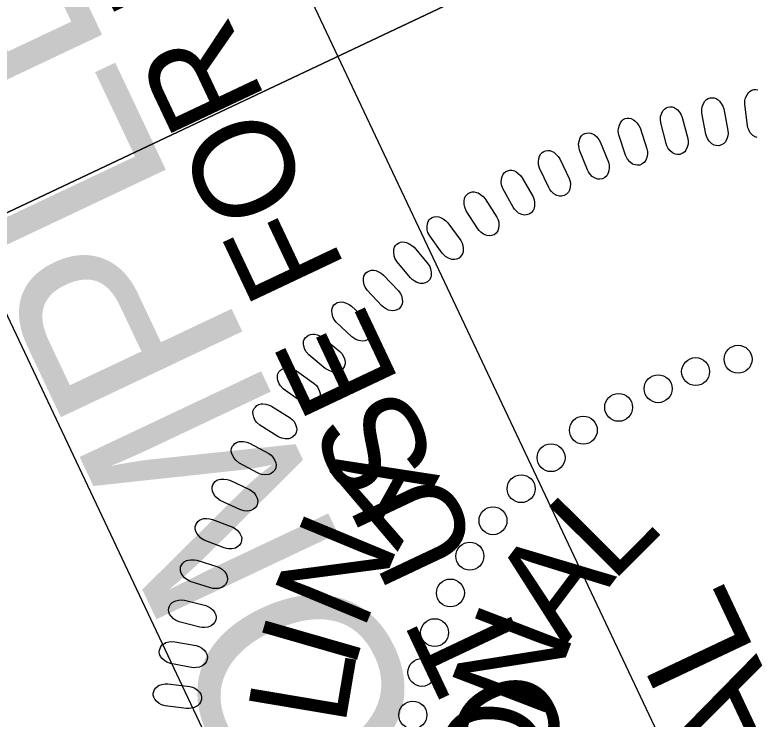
# Model space of a CAD drawing. Extents: x 476855 to 478565, y 498324 to 500313.
# Drawn here: x 476991.92 to 477034.48, y 499751.49 to 499791.92 of the extents above; entities that cross this region are included whole.
import ezdxf

# ---------------------------------------------------------------- set-up
doc = ezdxf.new("R2010")
doc.units = 0
for name, color, linetype in [('Sheet PE Seal Cell', 7, 'Continuous'), ('Sheet Plan CELL', 7, 'Continuous'), ('Sheet Sticker Incomplete CELL', 7, 'Continuous')]:
    doc.layers.add(name, color=color, linetype=linetype)

msp = doc.modelspace()

# ---------------------------------------------------------------- linework, layer by layer
at = {"layer": 'Sheet PE Seal Cell'}
msp.add_lwpolyline([(477034.529, 499784.874), (477034.419, 499784.91), (477034.28, 499784.993), (477034.141, 499785.146), (477034.051, 499785.316), (477034.005, 499785.44), (477033.974, 499785.567), (477033.818, 499786.784), (477033.828, 499787.006), (477033.861, 499787.152), (477033.952, 499787.334), (477034.034, 499787.455), (477034.135, 499787.548), (477034.234, 499787.601), (477034.342, 499787.635), (477034.456, 499787.629), (477034.579, 499787.614)], dxfattribs=at)
for points in [[(477031.59, 499785.073), (477031.358, 499786.278), (477031.354, 499786.5), (477031.378, 499786.648), (477031.456, 499786.836), (477031.531, 499786.961), (477031.627, 499787.061), (477031.721, 499787.119), (477031.828, 499787.16), (477031.941, 499787.162), (477032.065, 499787.155), (477032.179, 499787.116), (477032.3, 499787.038), (477032.374, 499786.971), (477032.469, 499786.836), (477032.561, 499786.672), (477032.613, 499786.519), (477032.858, 499785.287), (477032.867, 499785.116), (477032.85, 499784.97), (477032.792, 499784.797), (477032.708, 499784.639), (477032.628, 499784.542), (477032.485, 499784.453), (477032.342, 499784.405), (477032.187, 499784.416), (477032.075, 499784.446), (477031.931, 499784.519), (477031.783, 499784.664), (477031.682, 499784.828), (477031.629, 499784.949)], [(477029.305, 499784.526), (477028.999, 499785.714), (477028.98, 499785.935), (477028.995, 499786.084), (477029.062, 499786.276), (477029.129, 499786.407), (477029.217, 499786.512), (477029.308, 499786.577), (477029.412, 499786.624), (477029.525, 499786.633), (477029.649, 499786.634), (477029.765, 499786.602), (477029.891, 499786.531), (477029.969, 499786.469), (477030.072, 499786.341), (477030.174, 499786.182), (477030.236, 499786.034), (477030.557, 499784.819), (477030.578, 499784.649), (477030.569, 499784.502), (477030.522, 499784.325), (477030.449, 499784.162), (477030.375, 499784.061), (477030.238, 499783.963), (477030.098, 499783.907), (477029.943, 499783.908), (477029.829, 499783.93), (477029.681, 499783.995), (477029.524, 499784.129), (477029.413, 499784.287), (477029.353, 499784.404)], [(477026.977, 499783.865), (477026.597, 499785.031), (477026.564, 499785.251), (477026.57, 499785.4), (477026.624, 499785.597), (477026.683, 499785.731), (477026.764, 499785.841), (477026.851, 499785.912), (477026.953, 499785.965), (477027.065, 499785.981), (477027.188, 499785.99), (477027.306, 499785.966), (477027.436, 499785.903), (477027.517, 499785.846), (477027.628, 499785.725), (477027.74, 499785.573), (477027.812, 499785.428), (477028.208, 499784.235), (477028.24, 499784.067), (477028.24, 499783.92), (477028.205, 499783.741), (477028.142, 499783.574), (477028.074, 499783.468), (477027.943, 499783.362), (477027.807, 499783.297), (477027.652, 499783.289), (477027.538, 499783.303), (477027.386, 499783.358), (477027.22, 499783.483), (477027.1, 499783.633), (477027.032, 499783.747)], [(477024.791, 499783.016), (477024.337, 499784.156), (477024.292, 499784.373), (477024.288, 499784.522), (477024.33, 499784.722), (477024.38, 499784.86), (477024.454, 499784.975), (477024.536, 499785.05), (477024.634, 499785.111), (477024.745, 499785.133), (477024.867, 499785.15), (477024.987, 499785.133), (477025.121, 499785.079), (477025.206, 499785.027), (477025.324, 499784.912), (477025.446, 499784.768), (477025.525, 499784.627), (477025.996, 499783.463), (477026.038, 499783.297), (477026.048, 499783.15), (477026.024, 499782.969), (477025.971, 499782.798), (477025.91, 499782.688), (477025.786, 499782.574), (477025.654, 499782.501), (477025.501, 499782.483), (477025.385, 499782.49), (477025.231, 499782.536), (477025.057, 499782.649), (477024.928, 499782.792), (477024.853, 499782.9)], [(477022.57, 499782.003), (477022.046, 499783.113), (477021.986, 499783.327), (477021.974, 499783.475), (477022.003, 499783.677), (477022.043, 499783.817), (477022.111, 499783.937), (477022.189, 499784.017), (477022.282, 499784.084), (477022.392, 499784.113), (477022.513, 499784.138), (477022.633, 499784.128), (477022.77, 499784.083), (477022.858, 499784.036), (477022.983, 499783.929), (477023.114, 499783.793), (477023.202, 499783.658), (477023.746, 499782.525), (477023.797, 499782.362), (477023.816, 499782.216), (477023.803, 499782.034), (477023.762, 499781.86), (477023.708, 499781.746), (477023.592, 499781.625), (477023.465, 499781.543), (477023.312, 499781.516), (477023.197, 499781.516), (477023.039, 499781.551), (477022.859, 499781.654), (477022.721, 499781.788), (477022.639, 499781.892)], [(477020.527, 499780.872), (477019.935, 499781.947), (477019.862, 499782.157), (477019.839, 499782.304), (477019.856, 499782.507), (477019.888, 499782.65), (477019.948, 499782.774), (477020.02, 499782.859), (477020.109, 499782.931), (477020.216, 499782.968), (477020.336, 499782.999), (477020.456, 499782.997), (477020.596, 499782.961), (477020.687, 499782.919), (477020.818, 499782.821), (477020.957, 499782.693), (477021.054, 499782.564), (477021.667, 499781.467), (477021.729, 499781.308), (477021.757, 499781.163), (477021.756, 499780.981), (477021.725, 499780.805), (477021.679, 499780.688), (477021.57, 499780.559), (477021.448, 499780.47), (477021.299, 499780.433), (477021.183, 499780.426), (477021.023, 499780.452), (477020.837, 499780.542), (477020.691, 499780.667), (477020.602, 499780.766)], [(477018.493, 499779.642), (477017.834, 499780.677), (477017.748, 499780.882), (477017.717, 499781.028), (477017.72, 499781.231), (477017.743, 499781.376), (477017.795, 499781.503), (477017.862, 499781.593), (477017.946, 499781.67), (477018.051, 499781.713), (477018.168, 499781.752), (477018.289, 499781.759), (477018.43, 499781.73), (477018.523, 499781.695), (477018.661, 499781.605), (477018.808, 499781.486), (477018.913, 499781.363), (477019.594, 499780.307), (477019.665, 499780.152), (477019.702, 499780.01), (477019.712, 499779.827), (477019.693, 499779.649), (477019.654, 499779.53), (477019.554, 499779.395), (477019.438, 499779.298), (477019.29, 499779.251), (477019.175, 499779.238), (477019.015, 499779.253), (477018.823, 499779.332), (477018.67, 499779.447), (477018.575, 499779.541)], [(477016.457, 499778.24), (477015.735, 499779.231), (477015.636, 499779.431), (477015.596, 499779.574), (477015.587, 499779.777), (477015.601, 499779.923), (477015.644, 499780.054), (477015.705, 499780.147), (477015.784, 499780.23), (477015.887, 499780.279), (477016.002, 499780.326), (477016.121, 499780.339), (477016.264, 499780.32), (477016.359, 499780.291), (477016.502, 499780.209), (477016.656, 499780.099), (477016.768, 499779.984), (477017.514, 499778.972), (477017.596, 499778.822), (477017.641, 499778.683), (477017.663, 499778.501), (477017.655, 499778.323), (477017.623, 499778.201), (477017.532, 499778.059), (477017.422, 499777.956), (477017.278, 499777.9), (477017.164, 499777.879), (477017.003, 499777.884), (477016.807, 499777.951), (477016.645, 499778.057), (477016.546, 499778.144)], [(477014.637, 499776.816), (477013.854, 499777.76), (477013.743, 499777.952), (477013.693, 499778.093), (477013.671, 499778.296), (477013.676, 499778.442), (477013.712, 499778.575), (477013.767, 499778.672), (477013.841, 499778.759), (477013.939, 499778.816), (477014.051, 499778.869), (477014.169, 499778.89), (477014.313, 499778.88), (477014.411, 499778.857), (477014.558, 499778.784), (477014.719, 499778.684), (477014.838, 499778.576), (477015.645, 499777.614), (477015.736, 499777.469), (477015.791, 499777.333), (477015.824, 499777.153), (477015.827, 499776.974), (477015.803, 499776.85), (477015.721, 499776.704), (477015.618, 499776.593), (477015.477, 499776.529), (477015.365, 499776.5), (477015.204, 499776.496), (477015.004, 499776.549), (477014.837, 499776.645), (477014.731, 499776.726)], [(477012.991, 499775.214), (477012.149, 499776.107), (477012.026, 499776.293), (477011.968, 499776.43), (477011.934, 499776.63), (477011.929, 499776.777), (477011.956, 499776.912), (477012.005, 499777.012), (477012.074, 499777.104), (477012.169, 499777.166), (477012.276, 499777.226), (477012.393, 499777.254), (477012.538, 499777.254), (477012.636, 499777.237), (477012.789, 499777.174), (477012.954, 499777.084), (477013.081, 499776.984), (477013.947, 499776.074), (477014.047, 499775.935), (477014.109, 499775.802), (477014.154, 499775.625), (477014.168, 499775.447), (477014.152, 499775.321), (477014.079, 499775.17), (477013.984, 499775.053), (477013.847, 499774.98), (477013.737, 499774.945), (477013.576, 499774.93), (477013.373, 499774.971), (477013.2, 499775.056), (477013.09, 499775.13)], [(477011.272, 499773.435), (477010.376, 499774.273), (477010.242, 499774.451), (477010.175, 499774.584), (477010.128, 499774.782), (477010.115, 499774.928), (477010.133, 499775.064), (477010.176, 499775.168), (477010.238, 499775.264), (477010.329, 499775.331), (477010.433, 499775.398), (477010.547, 499775.434), (477010.692, 499775.442), (477010.791, 499775.431), (477010.947, 499775.378), (477011.119, 499775.299), (477011.25, 499775.206), (477012.172, 499774.353), (477012.281, 499774.221), (477012.352, 499774.092), (477012.407, 499773.918), (477012.433, 499773.741), (477012.424, 499773.615), (477012.36, 499773.459), (477012.273, 499773.337), (477012.142, 499773.255), (477012.033, 499773.213), (477011.874, 499773.188), (477011.669, 499773.217), (477011.491, 499773.29), (477011.376, 499773.357)], [(477009.736, 499771.626), (477008.79, 499772.406), (477008.645, 499772.575), (477008.57, 499772.704), (477008.511, 499772.899), (477008.488, 499773.043), (477008.498, 499773.181), (477008.533, 499773.287), (477008.59, 499773.386), (477008.676, 499773.46), (477008.776, 499773.533), (477008.888, 499773.576), (477009.032, 499773.593), (477009.131, 499773.588), (477009.29, 499773.545), (477009.466, 499773.476), (477009.603, 499773.392), (477010.578, 499772.598), (477010.694, 499772.473), (477010.773, 499772.35), (477010.839, 499772.179), (477010.875, 499772.004), (477010.875, 499771.878), (477010.821, 499771.719), (477010.741, 499771.591), (477010.616, 499771.501), (477010.51, 499771.452), (477010.353, 499771.417), (477010.146, 499771.433), (477009.964, 499771.495), (477009.846, 499771.555)], [(477008.326, 499769.735), (477007.333, 499770.454), (477007.177, 499770.614), (477007.094, 499770.737), (477007.022, 499770.928), (477006.991, 499771.071), (477006.992, 499771.209), (477007.022, 499771.317), (477007.071, 499771.419), (477007.153, 499771.498), (477007.247, 499771.577), (477007.357, 499771.627), (477007.499, 499771.654), (477007.599, 499771.655), (477007.76, 499771.622), (477007.94, 499771.565), (477008.082, 499771.49), (477009.104, 499770.758), (477009.229, 499770.64), (477009.316, 499770.522), (477009.391, 499770.356), (477009.439, 499770.184), (477009.447, 499770.058), (477009.403, 499769.896), (477009.332, 499769.763), (477009.212, 499769.665), (477009.11, 499769.609), (477008.954, 499769.565), (477008.747, 499769.568), (477008.562, 499769.619), (477008.439, 499769.671)], [(477007.012, 499767.719), (477005.975, 499768.374), (477005.809, 499768.524), (477005.719, 499768.642), (477005.636, 499768.828), (477005.595, 499768.969), (477005.587, 499769.106), (477005.61, 499769.216), (477005.653, 499769.321), (477005.73, 499769.405), (477005.819, 499769.49), (477005.925, 499769.547), (477006.066, 499769.582), (477006.165, 499769.59), (477006.328, 499769.566), (477006.511, 499769.521), (477006.658, 499769.455), (477007.724, 499768.79), (477007.855, 499768.68), (477007.949, 499768.567), (477008.036, 499768.406), (477008.094, 499768.236), (477008.11, 499768.111), (477008.076, 499767.947), (477008.013, 499767.81), (477007.9, 499767.705), (477007.801, 499767.643), (477007.649, 499767.589), (477007.442, 499767.579), (477007.254, 499767.618), (477007.129, 499767.662)], [(477005.85, 499765.621), (477004.775, 499766.211), (477004.6, 499766.349), (477004.503, 499766.462), (477004.408, 499766.642), (477004.359, 499766.78), (477004.342, 499766.916), (477004.358, 499767.027), (477004.394, 499767.135), (477004.466, 499767.224), (477004.549, 499767.314), (477004.652, 499767.377), (477004.79, 499767.421), (477004.889, 499767.435), (477005.052, 499767.422), (477005.238, 499767.389), (477005.389, 499767.332), (477006.495, 499766.734), (477006.632, 499766.633), (477006.734, 499766.526), (477006.83, 499766.371), (477006.899, 499766.206), (477006.922, 499766.082), (477006.899, 499765.916), (477006.845, 499765.775), (477006.738, 499765.663), (477006.644, 499765.596), (477006.495, 499765.532), (477006.289, 499765.508), (477006.099, 499765.535), (477005.971, 499765.572)], [(477004.827, 499763.522), (477003.716, 499764.043), (477003.533, 499764.17), (477003.429, 499764.277), (477003.323, 499764.45), (477003.265, 499764.585), (477003.24, 499764.72), (477003.249, 499764.832), (477003.278, 499764.942), (477003.344, 499765.035), (477003.422, 499765.13), (477003.52, 499765.2), (477003.655, 499765.252), (477003.753, 499765.273), (477003.917, 499765.27), (477004.104, 499765.247), (477004.258, 499765.2), (477005.399, 499764.673), (477005.543, 499764.581), (477005.651, 499764.481), (477005.757, 499764.332), (477005.836, 499764.171), (477005.867, 499764.049), (477005.855, 499763.882), (477005.809, 499763.738), (477005.709, 499763.62), (477005.62, 499763.546), (477005.476, 499763.474), (477005.272, 499763.437), (477005.08, 499763.453), (477004.95, 499763.481)], [(477003.936, 499761.319), (477002.795, 499761.769), (477002.605, 499761.884), (477002.494, 499761.984), (477002.377, 499762.15), (477002.311, 499762.281), (477002.278, 499762.414), (477002.279, 499762.527), (477002.302, 499762.638), (477002.362, 499762.735), (477002.433, 499762.836), (477002.527, 499762.911), (477002.658, 499762.972), (477002.755, 499762.998), (477002.918, 499763.005), (477003.107, 499762.996), (477003.264, 499762.958), (477004.436, 499762.503), (477004.585, 499762.42), (477004.699, 499762.327), (477004.814, 499762.186), (477004.903, 499762.03), (477004.942, 499761.91), (477004.94, 499761.742), (477004.903, 499761.596), (477004.812, 499761.471), (477004.727, 499761.392), (477004.587, 499761.311), (477004.386, 499761.262), (477004.194, 499761.265), (477004.062, 499761.285)], [(477003.151, 499759.018), (477001.983, 499759.396), (477001.786, 499759.498), (477001.669, 499759.591), (477001.542, 499759.75), (477001.468, 499759.876), (477001.426, 499760.007), (477001.421, 499760.119), (477001.436, 499760.232), (477001.49, 499760.333), (477001.555, 499760.437), (477001.644, 499760.519), (477001.771, 499760.587), (477001.866, 499760.62), (477002.029, 499760.638), (477002.218, 499760.639), (477002.376, 499760.612), (477003.574, 499760.232), (477003.729, 499760.158), (477003.848, 499760.073), (477003.972, 499759.938), (477004.07, 499759.789), (477004.116, 499759.671), (477004.125, 499759.504), (477004.098, 499759.355), (477004.014, 499759.226), (477003.934, 499759.142), (477003.801, 499759.051), (477003.602, 499758.989), (477003.411, 499758.981), (477003.278, 499758.992)], [(477002.539, 499756.769), (477001.35, 499757.073), (477001.147, 499757.163), (477001.024, 499757.248), (477000.887, 499757.399), (477000.805, 499757.52), (477000.756, 499757.649), (477000.743, 499757.759), (477000.752, 499757.874), (477000.798, 499757.977), (477000.857, 499758.086), (477000.941, 499758.172), (477001.064, 499758.249), (477001.156, 499758.287), (477001.317, 499758.315), (477001.506, 499758.329), (477001.666, 499758.311), (477002.885, 499758.008), (477003.045, 499757.944), (477003.169, 499757.866), (477003.301, 499757.739), (477003.409, 499757.596), (477003.462, 499757.482), (477003.481, 499757.315), (477003.463, 499757.166), (477003.388, 499757.03), (477003.314, 499756.941), (477003.185, 499756.843), (477002.992, 499756.77), (477002.801, 499756.748), (477002.668, 499756.752)], [(477002.068, 499754.451), (477000.863, 499754.679), (477000.653, 499754.757), (477000.526, 499754.834), (477000.38, 499754.976), (477000.291, 499755.092), (477000.233, 499755.216), (477000.214, 499755.328), (477000.215, 499755.441), (477000.255, 499755.548), (477000.307, 499755.659), (477000.385, 499755.751), (477000.503, 499755.835), (477000.592, 499755.88), (477000.752, 499755.918), (477000.939, 499755.943), (477001.1, 499755.935), (477002.336, 499755.709), (477002.498, 499755.655), (477002.627, 499755.585), (477002.767, 499755.468), (477002.884, 499755.331), (477002.944, 499755.22), (477002.974, 499755.055), (477002.965, 499754.905), (477002.899, 499754.765), (477002.83, 499754.672), (477002.709, 499754.565), (477002.519, 499754.48), (477002.33, 499754.447), (477002.197, 499754.442)], [(477001.771, 499752.099), (477000.554, 499752.251), (477000.341, 499752.315), (477000.209, 499752.385), (477000.054, 499752.517), (476999.957, 499752.627), (476999.892, 499752.748), (476999.866, 499752.857), (476999.86, 499752.971), (476999.893, 499753.08), (476999.938, 499753.194), (477000.01, 499753.291), (477000.122, 499753.382), (477000.209, 499753.432), (477000.366, 499753.48), (477000.551, 499753.517), (477000.712, 499753.52), (477001.96, 499753.371), (477002.125, 499753.328), (477002.258, 499753.266), (477002.406, 499753.157), (477002.53, 499753.029), (477002.598, 499752.922), (477002.638, 499752.759), (477002.638, 499752.608), (477002.581, 499752.465), (477002.518, 499752.367), (477002.403, 499752.253), (477002.22, 499752.156), (477002.034, 499752.111), (477001.901, 499752.098)]]:
    msp.add_lwpolyline(points, close=True, dxfattribs=at)
for centre in [(477033.441, 499772.152), (477031.002, 499771.44), (477028.852, 499770.457), (477026.583, 499769.386), (477024.557, 499768.077), (477022.704, 499766.498), (477020.988, 499764.719), (477019.37, 499762.879), (477018.041, 499760.843), (477016.924, 499758.73), (477016.017, 499756.453), (477015.288, 499754.171), (477014.769, 499751.725)]:
    msp.add_circle(centre, 0.801, dxfattribs=at)
at = {"layer": 'Sheet Plan CELL'}
msp.add_line((476959.595, 499765.507), (477061.271, 499813.569), dxfattribs=at)
for points in [[(476959.595, 499765.507), (476916.863, 499855.903), (477018.584, 499903.986), (477061.321, 499813.579)], [(477002.343, 499675.049), (476959.595, 499765.507), (477061.321, 499813.579), (477104.041, 499723.121)]]:
    msp.add_lwpolyline(points, close=True, dxfattribs=at)
at = {"layer": 'Sheet Sticker Incomplete CELL'}
msp.add_lwpolyline([(477041.856, 499723.087), (477020.609, 499713.046), (476957.802, 499845.953), (476979.049, 499855.994)], close=True, dxfattribs=at)

# ---------------------------------------------------------------- texts
at = {"layer": 'Sheet PE Seal Cell'}
for s, height, rotation, p in [('A', 5.669, 60.9666, (477013.89, 499761.078)), ('L', 5.669, 45.1247, (477026.178, 499759.262)), ('N', 5.669, 67.456, (477011.891, 499756.461)), ('A', 5.669, 53.0645, (477023.473, 499755.635)), ('SEAL', 6.2363, 115.2752, (477041.61, 499740.207)), ('N', 5.669, 68.9441, (477022.114, 499751.301)), ('I', 5.669, 73.9453, (477011.378, 499754.222)), ('L', 5.669, 80.4347, (477010.853, 499750.995)), ('O', 5.669, 84.8236, (477021.873, 499746.418))]:
    msp.add_text(s, height=height, rotation=rotation, dxfattribs=at).set_placement(p)
at = {"layer": 'Sheet Sticker Incomplete CELL'}
for s, height, p in [('INCOMPLETE PLANS', 11.52, (477027.454, 499726.18)), ('DO NOT USE FOR R/W ACQUISITION', 5.76, (477032.349, 499732.088))]:
    msp.add_text(s, height=height, rotation=115.2938, dxfattribs=at).set_placement(p)

doc.saveas('drawing.dxf')
